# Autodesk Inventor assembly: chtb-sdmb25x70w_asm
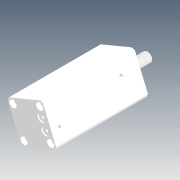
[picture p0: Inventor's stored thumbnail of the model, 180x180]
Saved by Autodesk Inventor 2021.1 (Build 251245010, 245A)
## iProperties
Company: Microsoft
Created: 2018-05
Part Number: chtb-sdmb25x70w_asm
Description: STEP AP214
Document SubType Name: Assembly
Designer: user
Title: chtb-sdmb25x70w_asm.STEP
Author: Windows
Revision Number: ÈÎºÎ
Sending System: SolidWorks 2015
Preprocessor: SwSTEP 2.0
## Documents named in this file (4)
- D:\Vault_2016\Projekty\Clamptek\Hydraulic\CHTB\CHTB-25\Inventor\chtb-sdmb25x70w\chtb-sdmb25x70w_asm.iam
- D:\Vault_2016\Projekty\Clamptek\Hydraulic\CHTB\CHTB-25\Inventor\chtb-sdmb25x70w\CHTB-25QG.ipt
- D:\Vault_2016\Projekty\Clamptek\Hydraulic\CHTB\CHTB-25\Inventor\chtb-sdmb25x70w\CHTB-SDMB25X70NBT.ipt
- D:\Vault_2016\Projekty\Clamptek\Hydraulic\CHTB\CHTB-25\Inventor\chtb-sdmb25x70w\CHTB-SDMB25X70WHSG.ipt
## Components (3 placed, 3 different names)
1. CHTB-25QG_1
2. CHTB-SDMB25X70NBT_2
3. CHTB-SDMB25X70WHSG_3
